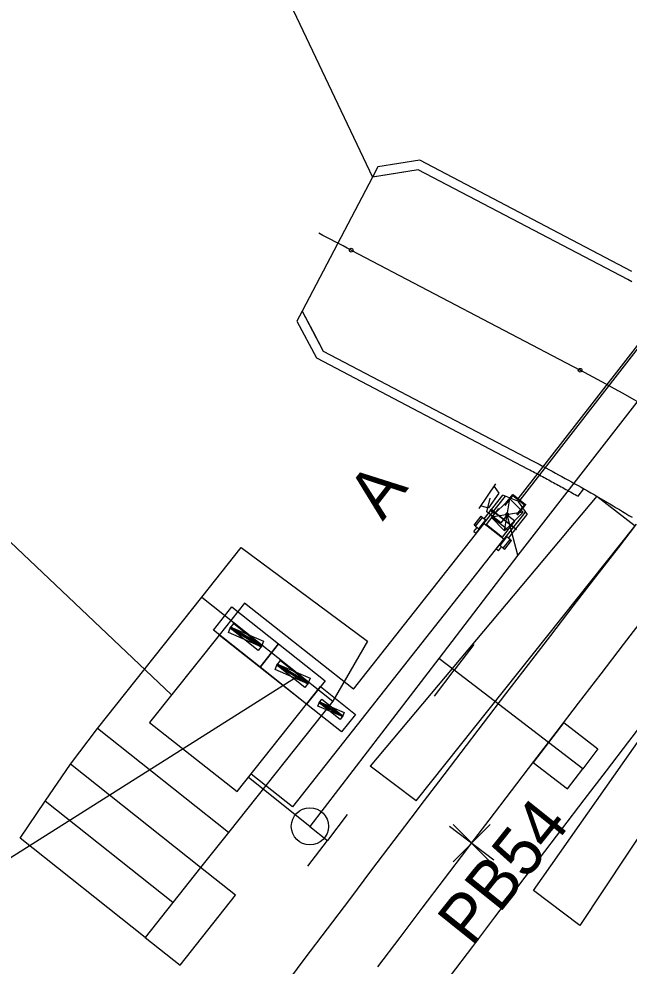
# Model space of a CAD drawing. Extents: x -541464 to -539952, y -1188799 to -1187382.
# Drawn here: x -541090.11 to -541073.7, y -1188386.78 to -1188361.32 of the extents above; entities that cross this region are included whole.
import ezdxf

# ---------------------------------------------------------------- set-up
doc = ezdxf.new("R2010")
doc.units = 0
for name, color, linetype in [('PS 01-01-31', 7, 'Continuous'), ('PS 01-72-01', 7, 'Continuous'), ('SO 01-10-01', 7, 'Continuous'), ('SO 01-13-01', 7, 'Continuous'), ('SO 01-86-01', 7, 'Continuous')]:
    doc.layers.add(name, color=color, linetype=linetype)

msp = doc.modelspace()

# ---------------------------------------------------------------- linework, layer by layer
at = {"layer": 'PS 01-01-31'}
for p, q in [((-541070.418, -1188367.659), (-541076.695, -1188375.733)), ((-541076.681, -1188374.218), (-541072.692, -1188369.086)), ((-541072.652, -1188369.117), (-541076.642, -1188374.249)), ((-541077.735, -1188374.479), (-541077.285, -1188373.817)), ((-541077.335, -1188373.89), (-541077.209, -1188374.062)), ((-541077.815, -1188375.143), (-541077.026, -1188374.146)), ((-541077.601, -1188374.751), (-541077.098, -1188374.116)), ((-541077.526, -1188374.569), (-541077.442, -1188374.202)), ((-541077.209, -1188374.062), (-541077.479, -1188374.458)), ((-541076.906, -1188374.213), (-541077.413, -1188374.711)), ((-541076.695, -1188374.283), (-541077.098, -1188374.116)), ((-541077.055, -1188374.38), (-541076.832, -1188374.1)), ((-541077.055, -1188375.075), (-541076.906, -1188374.213)), ((-541077.037, -1188374.394), (-541076.815, -1188374.114)), ((-541076.549, -1188374.577), (-541076.906, -1188374.213)), ((-541076.832, -1188374.1), (-541076.815, -1188374.114)), ((-541076.827, -1188374.13), (-541076.512, -1188374.376)), ((-541076.815, -1188374.114), (-541076.499, -1188374.36)), ((-541076.681, -1188374.218), (-541076.642, -1188374.249)), ((-541077.683, -1188374.402), (-541077.479, -1188374.458)), ((-541077.538, -1188374.903), (-541077.203, -1188374.48)), ((-541076.724, -1188374.642), (-541076.499, -1188374.36)), ((-541076.706, -1188374.657), (-541076.482, -1188374.374)), ((-541076.695, -1188374.283), (-541076.44, -1188374.637)), ((-541076.499, -1188374.36), (-541076.482, -1188374.374)), ((-541077.87, -1188374.921), (-541077.683, -1188374.686)), ((-541077.83, -1188374.952), (-541077.644, -1188374.717)), ((-541077.644, -1188374.717), (-541077.683, -1188374.686)), ((-541077.644, -1188374.717), (-541077.558, -1188374.785)), ((-541077.151, -1188374.862), (-541077.526, -1188374.569)), ((-541077.448, -1188374.515), (-541077.314, -1188374.621)), ((-541077.429, -1188374.492), (-541076.731, -1188375.044)), ((-541076.549, -1188374.577), (-541077.413, -1188374.711)), ((-541077.413, -1188374.711), (-541077.055, -1188375.075)), ((-541076.75, -1188375.029), (-541077.409, -1188374.508)), ((-541077.383, -1188374.707), (-541076.951, -1188375.049)), ((-541077.275, -1188375.571), (-541076.485, -1188374.574)), ((-541076.981, -1188374.644), (-541077.151, -1188374.862)), ((-541077.055, -1188375.075), (-541076.549, -1188374.577)), ((-541077.022, -1188374.634), (-541077.023, -1188374.638)), ((-541077.023, -1188374.638), (-541077.023, -1188374.643)), ((-541077.023, -1188374.643), (-541077.023, -1188374.647)), ((-541077.023, -1188374.647), (-541077.022, -1188374.651)), ((-541077.021, -1188374.63), (-541077.022, -1188374.634)), ((-541077.022, -1188374.651), (-541077.022, -1188374.655)), ((-541077.022, -1188374.655), (-541077.02, -1188374.659)), ((-541077.019, -1188374.627), (-541077.021, -1188374.63)), ((-541077.02, -1188374.659), (-541077.019, -1188374.663)), ((-541077.017, -1188374.623), (-541077.019, -1188374.627)), ((-541077.019, -1188374.663), (-541077.017, -1188374.666)), ((-541077.015, -1188374.619), (-541077.017, -1188374.623)), ((-541077.017, -1188374.666), (-541077.014, -1188374.67)), ((-541077.012, -1188374.616), (-541077.015, -1188374.619)), ((-541077.014, -1188374.67), (-541077.014, -1188374.67)), ((-541077.014, -1188374.67), (-541077.014, -1188374.67)), ((-541077.014, -1188374.67), (-541077.012, -1188374.673)), ((-541077.009, -1188374.613), (-541077.012, -1188374.616)), ((-541077.012, -1188374.673), (-541077.009, -1188374.676)), ((-541077.006, -1188374.611), (-541077.009, -1188374.613)), ((-541077.009, -1188374.676), (-541077.005, -1188374.678)), ((-541077.003, -1188374.608), (-541077.006, -1188374.611)), ((-541077.005, -1188374.678), (-541077.002, -1188374.681)), ((-541076.999, -1188374.606), (-541077.003, -1188374.608)), ((-541077.002, -1188374.681), (-541076.998, -1188374.683)), ((-541076.995, -1188374.605), (-541076.999, -1188374.606)), ((-541076.998, -1188374.683), (-541076.995, -1188374.684)), ((-541076.991, -1188374.603), (-541076.995, -1188374.605)), ((-541076.995, -1188374.684), (-541076.991, -1188374.685)), ((-541076.987, -1188374.603), (-541076.991, -1188374.603)), ((-541076.991, -1188374.685), (-541076.986, -1188374.686)), ((-541076.983, -1188374.602), (-541076.987, -1188374.603)), ((-541076.986, -1188374.686), (-541076.982, -1188374.686)), ((-541076.979, -1188374.602), (-541076.983, -1188374.602)), ((-541076.982, -1188374.686), (-541076.978, -1188374.686)), ((-541076.695, -1188375.733), (-541076.981, -1188374.644)), ((-541076.975, -1188374.602), (-541076.979, -1188374.602)), ((-541076.978, -1188374.686), (-541076.974, -1188374.686)), ((-541076.971, -1188374.603), (-541076.975, -1188374.602)), ((-541076.974, -1188374.686), (-541076.97, -1188374.685)), ((-541076.967, -1188374.604), (-541076.971, -1188374.603)), ((-541076.97, -1188374.685), (-541076.966, -1188374.684)), ((-541076.963, -1188374.606), (-541076.967, -1188374.604)), ((-541076.966, -1188374.684), (-541076.962, -1188374.682)), ((-541076.959, -1188374.608), (-541076.963, -1188374.606)), ((-541076.962, -1188374.682), (-541076.959, -1188374.68)), ((-541076.956, -1188374.61), (-541076.959, -1188374.608)), ((-541076.959, -1188374.68), (-541076.955, -1188374.678)), ((-541076.953, -1188374.613), (-541076.956, -1188374.61)), ((-541076.955, -1188374.678), (-541076.952, -1188374.675)), ((-541076.95, -1188374.615), (-541076.953, -1188374.613)), ((-541076.952, -1188374.675), (-541076.949, -1188374.672)), ((-541076.947, -1188374.619), (-541076.95, -1188374.615)), ((-541076.949, -1188374.672), (-541076.947, -1188374.669)), ((-541076.945, -1188374.622), (-541076.947, -1188374.619)), ((-541076.947, -1188374.669), (-541076.944, -1188374.665)), ((-541076.943, -1188374.626), (-541076.945, -1188374.622)), ((-541076.944, -1188374.665), (-541076.942, -1188374.662)), ((-541076.941, -1188374.629), (-541076.943, -1188374.626)), ((-541076.942, -1188375.272), (-541076.44, -1188374.637)), ((-541076.942, -1188374.662), (-541076.941, -1188374.658)), ((-541076.94, -1188374.633), (-541076.941, -1188374.629)), ((-541076.941, -1188374.658), (-541076.94, -1188374.654)), ((-541076.939, -1188374.637), (-541076.94, -1188374.633)), ((-541076.94, -1188374.654), (-541076.939, -1188374.65)), ((-541076.939, -1188374.642), (-541076.939, -1188374.637)), ((-541076.939, -1188374.646), (-541076.939, -1188374.642)), ((-541076.939, -1188374.65), (-541076.939, -1188374.646)), ((-541076.771, -1188374.821), (-541076.935, -1188374.691)), ((-541077.874, -1188375.096), (-541077.787, -1188374.986)), ((-541077.83, -1188374.952), (-541077.87, -1188374.921)), ((-541077.83, -1188374.952), (-541077.744, -1188375.02)), ((-541077.744, -1188375.02), (-541077.558, -1188374.785)), ((-541077.538, -1188374.903), (-541077.107, -1188375.245)), ((-541077.107, -1188375.245), (-541076.771, -1188374.821)), ((-541077.874, -1188375.096), (-541077.815, -1188375.143)), ((-541077.172, -1188375.474), (-541076.986, -1188375.238)), ((-541076.899, -1188375.307), (-541076.986, -1188375.238)), ((-541077.086, -1188375.542), (-541077.172, -1188375.474)), ((-541077.086, -1188375.542), (-541076.899, -1188375.307)), ((-541077.046, -1188375.573), (-541076.86, -1188375.338)), ((-541076.899, -1188375.307), (-541076.86, -1188375.338)), ((-541085.194, -1188376.856), (-541084.137, -1188375.526)), ((-541084.137, -1188375.526), (-541080.733, -1188378.041)), ((-541076.695, -1188375.733), (-541078.821, -1188378.506)), ((-541077.216, -1188375.617), (-541077.275, -1188375.571)), ((-541077.216, -1188375.617), (-541077.129, -1188375.508)), ((-541077.086, -1188375.542), (-541077.046, -1188375.573)), ((-541088, -1188380.389), (-541085.194, -1188376.856)), ((-541085.194, -1188376.856), (-541081.67, -1188379.655)), ((-541080.733, -1188378.041), (-541081.67, -1188379.655)), ((-541077.874, -1188378.129), (-541078.404, -1188378.826)), ((-541078.821, -1188378.506), (-541082.284, -1188383.021)), ((-541078.404, -1188378.826), (-541078.821, -1188378.506)), ((-541078.933, -1188379.523), (-541078.404, -1188378.826)), ((-541075.871, -1188380.768), (-541078.404, -1188378.826)), ((-541081.67, -1188379.655), (-541084.476, -1188383.187)), ((-541075.461, -1188380.232), (-541075.871, -1188380.768)), ((-541075.461, -1188380.232), (-541074.539, -1188380.939)), ((-541088.724, -1188381.345), (-541088, -1188380.389)), ((-541084.476, -1188383.187), (-541088, -1188380.389)), ((-541075.871, -1188380.768), (-541076.282, -1188381.304)), ((-541074.949, -1188381.475), (-541075.872, -1188380.768)), ((-541074.539, -1188380.939), (-541074.949, -1188381.475)), ((-541089.401, -1188382.341), (-541088.724, -1188381.345)), ((-541085.222, -1188384.127), (-541088.724, -1188381.345)), ((-541076.282, -1188381.304), (-541075.36, -1188382.011)), ((-541075.36, -1188382.011), (-541074.949, -1188381.475)), ((-541082.284, -1188383.021), (-541083.939, -1188381.707)), ((-541082.284, -1188383.021), (-541083.939, -1188381.707)), ((-541082.284, -1188383.021), (-541083.939, -1188381.707)), ((-541090.077, -1188383.336), (-541089.401, -1188382.341)), ((-541085.969, -1188385.067), (-541089.401, -1188382.341)), ((-541081.282, -1188382.7), (-541081.811, -1188383.397)), ((-541082.284, -1188383.021), (-541081.811, -1188383.397)), ((-541086.715, -1188386.006), (-541090.077, -1188383.336)), ((-541084.476, -1188383.187), (-541085.222, -1188384.127)), ((-541082.341, -1188384.093), (-541081.811, -1188383.397)), ((-541085.222, -1188384.127), (-541085.969, -1188385.067)), ((-541084.283, -1188384.874), (-541085.222, -1188384.127)), ((-541085.776, -1188386.753), (-541084.283, -1188384.874)), ((-541085.969, -1188385.067), (-541086.715, -1188386.006)), ((-541086.715, -1188386.006), (-541085.776, -1188386.753))]:
    msp.add_line(p, q, dxfattribs=at)
msp.add_circle((-541082.285, -1188383.022), 0.5, dxfattribs=at)
at = {"layer": 'PS 01-72-01'}
for p, q in [((-541163.896, -1188305.694), (-541086.005, -1188379.485)), ((-541081.115, -1188379.335), (-541077.6, -1188374.88)), ((-541077.6, -1188374.88), (-541077.074, -1188375.295)), ((-541077.074, -1188375.295), (-541082.754, -1188382.494)), ((-541084.042, -1188377.025), (-541084.729, -1188377.878)), ((-541081.115, -1188379.335), (-541084.042, -1188377.025)), ((-541084.728, -1188377.878), (-541086.594, -1188380.227)), ((-541082.373, -1188379.736), (-541084.728, -1188377.878)), ((-541084.239, -1188382.085), (-541082.373, -1188379.736)), ((-541086.594, -1188380.227), (-541084.239, -1188382.085)), ((-541082.754, -1188382.494), (-541083.866, -1188381.616))]:
    msp.add_line(p, q, dxfattribs=at)
at = {"layer": 'SO 01-10-01'}
for p, q in [((-541074.569, -1188374.149), (-541080.665, -1188381.4)), ((-541074.569, -1188374.149), (-541073.54, -1188374.944)), ((-541079.431, -1188382.338), (-541073.54, -1188374.944)), ((-541073.992, -1188375.53), (-541073.505, -1188374.898)), ((-541074.598, -1188376.315), (-541073.992, -1188375.53)), ((-541075.203, -1188377.101), (-541074.598, -1188376.315)), ((-541076.272, -1188384.741), (-541070.815, -1188376.977)), ((-541076.272, -1188384.741), (-541070.815, -1188376.977)), ((-541075.807, -1188377.887), (-541075.203, -1188377.101)), ((-541073.855, -1188378.137), (-541073.251, -1188377.352)), ((-541069.786, -1188377.772), (-541075.027, -1188385.689)), ((-541076.41, -1188378.674), (-541075.807, -1188377.887)), ((-541074.458, -1188378.922), (-541073.855, -1188378.137)), ((-541077.013, -1188379.461), (-541076.41, -1188378.674)), ((-541075.061, -1188379.708), (-541074.458, -1188378.922)), ((-541077.615, -1188380.248), (-541077.013, -1188379.461)), ((-541075.663, -1188380.494), (-541075.061, -1188379.708)), ((-541073.711, -1188380.742), (-541073.11, -1188379.957)), ((-541078.216, -1188381.037), (-541077.615, -1188380.248)), ((-541076.264, -1188381.28), (-541075.663, -1188380.494)), ((-541074.313, -1188381.527), (-541073.711, -1188380.742)), ((-541078.817, -1188381.825), (-541078.216, -1188381.037)), ((-541076.865, -1188382.067), (-541076.264, -1188381.28)), ((-541079.431, -1188382.338), (-541080.665, -1188381.4)), ((-541074.913, -1188382.312), (-541074.313, -1188381.527)), ((-541079.29, -1188382.446), (-541078.817, -1188381.825)), ((-541077.465, -1188382.855), (-541076.865, -1188382.067)), ((-541075.513, -1188383.098), (-541074.913, -1188382.312)), ((-541080.017, -1188383.403), (-541079.418, -1188382.614)), ((-541079.418, -1188382.614), (-541079.29, -1188382.446)), ((-541077.937, -1188383.475), (-541077.465, -1188382.855)), ((-541077.34, -1188383.929), (-541078.534, -1188383.021)), ((-541078.437, -1188382.975), (-541077.437, -1188383.975)), ((-541077.437, -1188382.975), (-541078.437, -1188383.975)), ((-541076.112, -1188383.885), (-541075.513, -1188383.098)), ((-541080.616, -1188384.193), (-541080.017, -1188383.403)), ((-541078.663, -1188384.431), (-541078.064, -1188383.643)), ((-541078.064, -1188383.643), (-541077.937, -1188383.475)), ((-541076.584, -1188384.504), (-541076.112, -1188383.885)), ((-541081.215, -1188384.984), (-541080.616, -1188384.193)), ((-541079.262, -1188385.22), (-541078.663, -1188384.431)), ((-541076.711, -1188384.672), (-541076.584, -1188384.504)), ((-541077.309, -1188385.459), (-541076.711, -1188384.672)), ((-541075.027, -1188385.689), (-541076.272, -1188384.741)), ((-541081.813, -1188385.774), (-541081.215, -1188384.984)), ((-541079.859, -1188386.009), (-541079.262, -1188385.22)), ((-541077.907, -1188386.247), (-541077.309, -1188385.459)), ((-541082.41, -1188386.565), (-541081.813, -1188385.774)), ((-541080.457, -1188386.799), (-541079.859, -1188386.009)), ((-541078.504, -1188387.035), (-541077.907, -1188386.247)), ((-541083.007, -1188387.357), (-541082.41, -1188386.565))]:
    msp.add_line(p, q, dxfattribs=at)
at = {"layer": 'SO 01-13-01'}
for p, q in [((-541100.781, -1188323.076), (-541080.603, -1188365.571)), ((-541080.458, -1188365.295), (-541080.603, -1188365.571)), ((-541079.327, -1188365.114), (-541080.458, -1188365.295)), ((-541073.625, -1188368.105), (-541079.327, -1188365.114)), ((-541080.603, -1188365.571), (-541082.493, -1188369.175)), ((-541080.603, -1188365.571), (-541082.493, -1188369.175)), ((-541080.603, -1188365.571), (-541082.493, -1188369.175)), ((-541079.37, -1188365.374), (-541080.603, -1188365.571)), ((-541079.986, -1188365.472), (-541080.603, -1188365.571)), ((-541079.37, -1188365.374), (-541079.986, -1188365.472)), ((-541073.741, -1188368.326), (-541079.37, -1188365.374)), ((-541081.173, -1188367.533), (-541075.019, -1188370.761)), ((-541073.626, -1188368.386), (-541073.741, -1188368.326)), ((-541073.741, -1188368.326), (-541073.741, -1188368.326)), ((-541082.493, -1188369.175), (-541082.634, -1188369.443)), ((-541082.493, -1188369.175), (-541081.925, -1188370.244)), ((-541082.493, -1188369.175), (-541082.209, -1188369.71)), ((-541082.634, -1188369.443), (-541082.109, -1188370.43)), ((-541082.209, -1188369.71), (-541081.925, -1188370.244)), ((-541081.925, -1188370.244), (-541076.296, -1188373.197)), ((-541082.109, -1188370.43), (-541076.412, -1188373.418)), ((-541076.296, -1188373.197), (-541076.296, -1188373.197)), ((-541076.296, -1188373.197), (-541076.208, -1188373.243)), ((-541076.412, -1188373.418), (-541076.412, -1188373.418)), ((-541076.412, -1188373.418), (-541076.37, -1188373.44)), ((-541076.37, -1188373.44), (-541076.328, -1188373.463)), ((-541076.208, -1188373.243), (-541076.121, -1188373.289)), ((-541076.121, -1188373.289), (-541076.033, -1188373.336)), ((-541076.033, -1188373.336), (-541075.945, -1188373.382)), ((-541075.945, -1188373.382), (-541075.858, -1188373.429)), ((-541075.858, -1188373.429), (-541075.771, -1188373.476)), ((-541076.328, -1188373.463), (-541076.285, -1188373.485)), ((-541076.285, -1188373.485), (-541076.243, -1188373.507)), ((-541076.243, -1188373.507), (-541076.201, -1188373.53)), ((-541076.201, -1188373.53), (-541076.159, -1188373.552)), ((-541076.159, -1188373.552), (-541076.116, -1188373.575)), ((-541076.116, -1188373.575), (-541076.074, -1188373.597)), ((-541076.074, -1188373.597), (-541076.032, -1188373.62)), ((-541076.032, -1188373.62), (-541075.99, -1188373.642)), ((-541075.99, -1188373.642), (-541075.948, -1188373.665)), ((-541075.948, -1188373.665), (-541075.906, -1188373.688)), ((-541075.906, -1188373.688), (-541075.864, -1188373.71)), ((-541075.864, -1188373.71), (-541075.822, -1188373.733)), ((-541075.771, -1188373.476), (-541075.684, -1188373.524)), ((-541075.684, -1188373.524), (-541075.597, -1188373.571)), ((-541075.597, -1188373.571), (-541075.51, -1188373.619)), ((-541075.51, -1188373.619), (-541075.423, -1188373.667)), ((-541075.423, -1188373.667), (-541075.336, -1188373.715)), ((-541075.336, -1188373.715), (-541075.249, -1188373.763)), ((-541075.822, -1188373.733), (-541075.78, -1188373.756)), ((-541075.78, -1188373.756), (-541075.738, -1188373.779)), ((-541075.738, -1188373.779), (-541075.696, -1188373.802)), ((-541075.696, -1188373.802), (-541075.654, -1188373.825)), ((-541075.654, -1188373.825), (-541075.612, -1188373.848)), ((-541075.612, -1188373.848), (-541075.57, -1188373.871)), ((-541075.57, -1188373.871), (-541075.528, -1188373.894)), ((-541075.528, -1188373.894), (-541075.487, -1188373.917)), ((-541075.487, -1188373.917), (-541075.445, -1188373.94)), ((-541075.445, -1188373.94), (-541075.403, -1188373.963)), ((-541075.403, -1188373.963), (-541075.361, -1188373.986)), ((-541075.249, -1188373.763), (-541075.163, -1188373.811)), ((-541075.163, -1188373.811), (-541075.076, -1188373.86)), ((-541075.076, -1188373.86), (-541074.99, -1188373.908)), ((-541075.07, -1188374.15), (-541074.917, -1188373.95)), ((-541074.99, -1188373.908), (-541074.903, -1188373.957)), ((-541074.903, -1188373.957), (-541074.817, -1188374.006)), ((-541075.361, -1188373.986), (-541075.32, -1188374.01)), ((-541075.32, -1188374.01), (-541075.278, -1188374.033)), ((-541075.278, -1188374.033), (-541075.236, -1188374.056)), ((-541075.236, -1188374.056), (-541075.195, -1188374.08)), ((-541075.195, -1188374.08), (-541075.153, -1188374.103)), ((-541075.153, -1188374.103), (-541075.111, -1188374.127)), ((-541075.111, -1188374.127), (-541075.07, -1188374.15)), ((-541074.817, -1188374.006), (-541074.731, -1188374.056)), ((-541074.731, -1188374.056), (-541074.645, -1188374.105)), ((-541074.645, -1188374.105), (-541074.559, -1188374.155)), ((-541074.559, -1188374.155), (-541074.474, -1188374.204)), ((-541074.474, -1188374.204), (-541074.388, -1188374.254)), ((-541074.388, -1188374.254), (-541074.302, -1188374.305)), ((-541074.302, -1188374.305), (-541074.217, -1188374.355)), ((-541074.217, -1188374.355), (-541074.132, -1188374.405)), ((-541074.132, -1188374.405), (-541074.046, -1188374.456)), ((-541074.046, -1188374.456), (-541073.961, -1188374.507)), ((-541073.961, -1188374.507), (-541073.876, -1188374.558)), ((-541073.876, -1188374.558), (-541073.791, -1188374.609)), ((-541073.791, -1188374.609), (-541073.706, -1188374.661)), ((-541073.706, -1188374.661), (-541073.622, -1188374.712))]:
    msp.add_line(p, q, dxfattribs=at)
for centre in [(-541081.174, -1188367.534), (-541075.019, -1188370.762)]:
    msp.add_circle(centre, 0.05, dxfattribs=at)
for centre, radius, start, end in [((-541185.218, -1188565.904), 224, 62.32328, 62.57501), ((-541098.243, -1188415.041), 50, 52.6833, 62.3233)]:
    msp.add_arc(centre, radius, start, end, dxfattribs=at)
at = {"layer": 'SO 01-86-01'}
for p, q in [((-541084.879, -1188377.746), (-541084.381, -1188377.12)), ((-541084.381, -1188377.12), (-541083.128, -1188378.115)), ((-541083.626, -1188378.741), (-541084.879, -1188377.746)), ((-541084.476, -1188377.814), (-541084.425, -1188377.697)), ((-541084.429, -1188377.694), (-541084.33, -1188377.569)), ((-541083.677, -1188378.292), (-541084.429, -1188377.694)), ((-541084.425, -1188377.697), (-541084.413, -1188377.667)), ((-541084.425, -1188377.697), (-541083.594, -1188378.194)), ((-541083.594, -1188378.194), (-541084.425, -1188377.697)), ((-541084.425, -1188377.697), (-541083.581, -1188378.164)), ((-541083.581, -1188378.164), (-541084.425, -1188377.697)), ((-541084.413, -1188377.667), (-541083.581, -1188378.164)), ((-541083.581, -1188378.164), (-541084.413, -1188377.667)), ((-541084.413, -1188377.667), (-541083.531, -1188378.047)), ((-541084.33, -1188377.569), (-541083.578, -1188378.166)), ((-541083.594, -1188378.194), (-541084.476, -1188377.814)), ((-541083.578, -1188378.166), (-541083.677, -1188378.292)), ((-541083.128, -1188378.115), (-541083.626, -1188378.741)), ((-541083.626, -1188378.741), (-541083.128, -1188378.115)), ((-541083.581, -1188378.164), (-541083.594, -1188378.194)), ((-541083.531, -1188378.047), (-541083.581, -1188378.164)), ((-541083.128, -1188378.115), (-541081.875, -1188379.11)), ((-541082.373, -1188379.736), (-541083.626, -1188378.741)), ((-541083.223, -1188378.809), (-541083.173, -1188378.692)), ((-541082.341, -1188379.189), (-541083.223, -1188378.809)), ((-541083.176, -1188378.69), (-541083.077, -1188378.564)), ((-541082.425, -1188379.287), (-541083.176, -1188378.69)), ((-541083.173, -1188378.692), (-541083.16, -1188378.662)), ((-541083.173, -1188378.692), (-541082.341, -1188379.189)), ((-541082.341, -1188379.189), (-541083.173, -1188378.692)), ((-541083.173, -1188378.692), (-541082.329, -1188379.159)), ((-541082.329, -1188379.159), (-541083.173, -1188378.692)), ((-541083.16, -1188378.662), (-541082.329, -1188379.159)), ((-541082.329, -1188379.159), (-541083.16, -1188378.662)), ((-541083.16, -1188378.662), (-541082.278, -1188379.042)), ((-541083.077, -1188378.564), (-541082.325, -1188379.161)), ((-541155.91, -1188425.271), (-541082.672, -1188379.02)), ((-541082.278, -1188379.042), (-541082.329, -1188379.159)), ((-541082.325, -1188379.161), (-541082.425, -1188379.287)), ((-541081.875, -1188379.11), (-541082.373, -1188379.736)), ((-541082.373, -1188379.736), (-541082, -1188379.266)), ((-541082.329, -1188379.159), (-541082.341, -1188379.189)), ((-541082, -1188379.266), (-541081.06, -1188380.013)), ((-541081.433, -1188380.483), (-541082.373, -1188379.736)), ((-541082.071, -1188379.787), (-541082.033, -1188379.699)), ((-541081.41, -1188380.072), (-541082.071, -1188379.787)), ((-541082.036, -1188379.698), (-541081.961, -1188379.604)), ((-541081.472, -1188380.145), (-541082.036, -1188379.698)), ((-541082.033, -1188379.699), (-541082.024, -1188379.677)), ((-541082.033, -1188379.699), (-541081.41, -1188380.072)), ((-541081.41, -1188380.072), (-541082.033, -1188379.699)), ((-541082.033, -1188379.699), (-541081.4, -1188380.05)), ((-541081.4, -1188380.05), (-541082.033, -1188379.699)), ((-541082.024, -1188379.677), (-541081.4, -1188380.05)), ((-541081.4, -1188380.05), (-541082.024, -1188379.677)), ((-541082.024, -1188379.677), (-541081.362, -1188379.962)), ((-541081.961, -1188379.604), (-541081.397, -1188380.052)), ((-541081.397, -1188380.052), (-541081.472, -1188380.145)), ((-541081.06, -1188380.013), (-541081.433, -1188380.483)), ((-541081.4, -1188380.05), (-541081.41, -1188380.072)), ((-541081.362, -1188379.962), (-541081.4, -1188380.05))]:
    msp.add_line(p, q, dxfattribs=at)

# ---------------------------------------------------------------- texts
at = {"layer": 'PS 01-01-31'}
for s, rotation, p in [('A', 52.1388, (-541080.328, -1188374.836)), ('PB54', 51.3155, (-541077.923, -1188386.293))]:
    msp.add_text(s, height=1.3, rotation=rotation, dxfattribs=at).set_placement(p)

doc.saveas('drawing.dxf')
